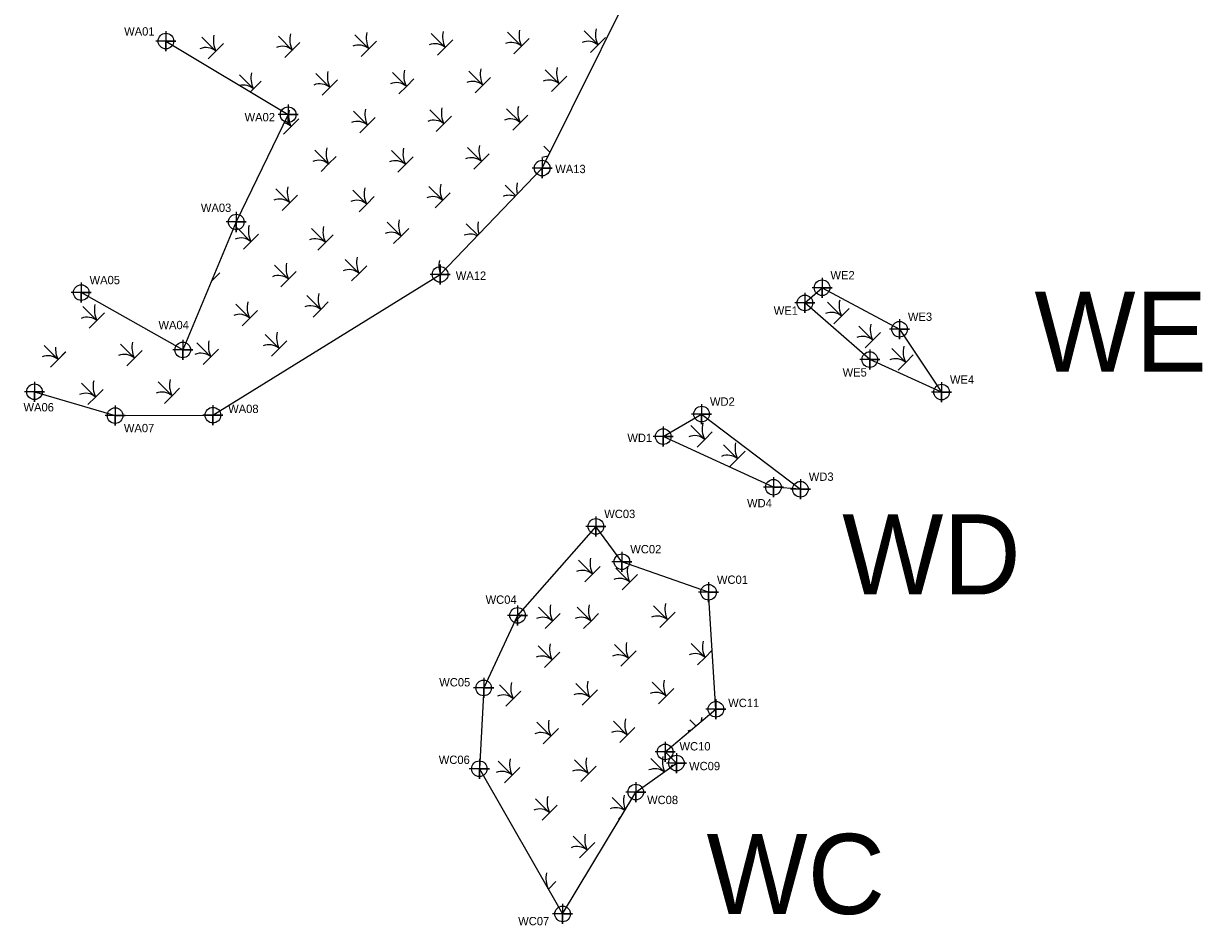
# Model space of a CAD drawing. Extents: x 2129042 to 2129395, y 148168 to 148691.
# Drawn here: x 2129042.3 to 2129395.4, y 148168.4 to 148438.5 of the extents above; entities that cross this region are included whole.
import ezdxf

# ---------------------------------------------------------------- set-up
doc = ezdxf.new("R2010")
doc.units = 0
for name, color, linetype in [('Default', 7, 'Continuous'), ('Exist Environmental Wetland Boundary', 7, 'Continuous'), ('Exist Environmental Wetland Boundary Cogo Number', 7, 'Continuous'), ('Exist Environmental Wetland Boundary Cogo Point CELL', 7, 'Continuous'), ('Exist Hydro Swamp or Marsh', 7, 'Continuous')]:
    doc.layers.add(name, color=color, linetype=linetype)

msp = doc.modelspace()

# ---------------------------------------------------------------- linework, layer by layer
at = {"layer": 'Exist Environmental Wetland Boundary'}
for points in [[(2129099.03, 148321.24), (2129167.08, 148363.39), (2129197.64, 148395.26), (2129233.05, 148466.61), (2129222.96, 148527.56), (2129235.22, 148526.74)], [(2129084.96, 148433.28), (2129121.56, 148411.25), (2129106.03, 148379.1), (2129089.99, 148340.77), (2129059.59, 148357.96)], [(2129276.33, 148354.86), (2129281.48, 148359.4), (2129304.68, 148346.97), (2129317.27, 148328.15), (2129295.76, 148337.9), (2129276.33, 148354.86)], [(2129045.59, 148328.24), (2129069.73, 148321.11), (2129099.03, 148321.24)], [(2129233.9, 148314.83), (2129245.4, 148321.55), (2129274.99, 148299.06), (2129266.91, 148299.65), (2129233.9, 148314.83)], [(2129247.48, 148268.2), (2129221.53, 148277.34), (2129213.73, 148287.91), (2129190.28, 148261.25), (2129180.12, 148239.54), (2129178.82, 148215.32), (2129203.77, 148171.84), (2129225.66, 148208.34), (2129237.86, 148217.02), (2129234.47, 148220.36), (2129249.69, 148233.15), (2129247.48, 148268.2)]]:
    msp.add_lwpolyline(points, dxfattribs=at)
at = {"layer": 'Exist Environmental Wetland Boundary Cogo Point CELL'}
for points in [[(2129084.96, 148436.28), (2129084.96, 148430.28), (2129084.96, 148433.28), (2129087.96, 148433.28), (2129081.96, 148433.28)], [(2129121.56, 148414.25), (2129121.56, 148408.25), (2129121.56, 148411.25), (2129124.56, 148411.25), (2129118.56, 148411.25)], [(2129197.64, 148398.26), (2129197.64, 148392.26), (2129197.64, 148395.26), (2129200.64, 148395.26), (2129194.64, 148395.26)], [(2129106.03, 148382.1), (2129106.03, 148376.1), (2129106.03, 148379.1), (2129109.03, 148379.1), (2129103.03, 148379.1)], [(2129167.08, 148366.39), (2129167.08, 148360.39), (2129167.08, 148363.39), (2129170.08, 148363.39), (2129164.08, 148363.39)], [(2129059.59, 148360.96), (2129059.59, 148354.96), (2129059.59, 148357.96), (2129062.59, 148357.96), (2129056.59, 148357.96)], [(2129281.48, 148362.4), (2129281.48, 148356.4), (2129281.48, 148359.4), (2129284.48, 148359.4), (2129278.48, 148359.4)], [(2129276.33, 148357.86), (2129276.33, 148351.86), (2129276.33, 148354.86), (2129279.33, 148354.86), (2129273.33, 148354.86)], [(2129304.68, 148349.97), (2129304.68, 148343.97), (2129304.68, 148346.97), (2129307.68, 148346.97), (2129301.68, 148346.97)], [(2129089.99, 148343.77), (2129089.99, 148337.77), (2129089.99, 148340.77), (2129092.99, 148340.77), (2129086.99, 148340.77)], [(2129295.76, 148340.9), (2129295.76, 148334.9), (2129295.76, 148337.9), (2129298.76, 148337.9), (2129292.76, 148337.9)], [(2129045.59, 148331.24), (2129045.59, 148325.24), (2129045.59, 148328.24), (2129048.59, 148328.24), (2129042.59, 148328.24)], [(2129317.27, 148331.15), (2129317.27, 148325.15), (2129317.27, 148328.15), (2129320.27, 148328.15), (2129314.27, 148328.15)], [(2129069.73, 148324.11), (2129069.73, 148318.11), (2129069.73, 148321.11), (2129072.73, 148321.11), (2129066.73, 148321.11)], [(2129099.03, 148324.24), (2129099.03, 148318.24), (2129099.03, 148321.24), (2129102.03, 148321.24), (2129096.03, 148321.24)], [(2129245.4, 148324.55), (2129245.4, 148318.55), (2129245.4, 148321.55), (2129248.4, 148321.55), (2129242.4, 148321.55)], [(2129233.9, 148317.83), (2129233.9, 148311.83), (2129233.9, 148314.83), (2129236.9, 148314.83), (2129230.9, 148314.83)], [(2129266.91, 148302.65), (2129266.91, 148296.65), (2129266.91, 148299.65), (2129269.91, 148299.65), (2129263.91, 148299.65)], [(2129274.99, 148302.06), (2129274.99, 148296.06), (2129274.99, 148299.06), (2129277.99, 148299.06), (2129271.99, 148299.06)], [(2129213.73, 148290.91), (2129213.73, 148284.91), (2129213.73, 148287.91), (2129216.73, 148287.91), (2129210.73, 148287.91)], [(2129221.53, 148280.34), (2129221.53, 148274.34), (2129221.53, 148277.34), (2129224.53, 148277.34), (2129218.53, 148277.34)], [(2129247.48, 148271.2), (2129247.48, 148265.2), (2129247.48, 148268.2), (2129250.48, 148268.2), (2129244.48, 148268.2)], [(2129190.28, 148264.25), (2129190.28, 148258.25), (2129190.28, 148261.25), (2129193.28, 148261.25), (2129187.28, 148261.25)], [(2129180.12, 148242.54), (2129180.12, 148236.54), (2129180.12, 148239.54), (2129183.12, 148239.54), (2129177.12, 148239.54)], [(2129249.69, 148236.15), (2129249.69, 148230.15), (2129249.69, 148233.15), (2129252.69, 148233.15), (2129246.69, 148233.15)], [(2129234.47, 148223.36), (2129234.47, 148217.36), (2129234.47, 148220.36), (2129237.47, 148220.36), (2129231.47, 148220.36)], [(2129237.86, 148220.02), (2129237.86, 148214.02), (2129237.86, 148217.02), (2129240.86, 148217.02), (2129234.86, 148217.02)], [(2129178.82, 148218.32), (2129178.82, 148212.32), (2129178.82, 148215.32), (2129181.82, 148215.32), (2129175.82, 148215.32)], [(2129225.66, 148211.34), (2129225.66, 148205.34), (2129225.66, 148208.34), (2129228.66, 148208.34), (2129222.66, 148208.34)], [(2129203.77, 148174.84), (2129203.77, 148168.84), (2129203.77, 148171.84), (2129206.77, 148171.84), (2129200.77, 148171.84)]]:
    msp.add_lwpolyline(points, dxfattribs=at)
for centre in [(2129084.96, 148433.28), (2129121.56, 148411.25), (2129197.64, 148395.26), (2129106.03, 148379.1), (2129167.08, 148363.39), (2129281.48, 148359.4), (2129059.59, 148357.96), (2129276.33, 148354.86), (2129304.68, 148346.97), (2129089.99, 148340.77), (2129295.76, 148337.9), (2129045.59, 148328.24), (2129317.27, 148328.15), (2129069.73, 148321.11), (2129099.03, 148321.24), (2129245.4, 148321.55), (2129233.9, 148314.83), (2129266.91, 148299.65), (2129274.99, 148299.06), (2129213.73, 148287.91), (2129221.53, 148277.34), (2129247.48, 148268.2), (2129190.28, 148261.25), (2129180.12, 148239.54), (2129249.69, 148233.15), (2129234.47, 148220.36), (2129237.86, 148217.02), (2129178.82, 148215.32), (2129225.66, 148208.34), (2129203.77, 148171.84)]:
    msp.add_circle(centre, 2.34, dxfattribs=at)
at = {"layer": 'Exist Hydro Swamp or Marsh'}
for p, q in [((2129179.43, 148226.74), (2129179.65, 148226.96)), ((2129235.74, 148215.52), (2129236.68, 148216.45)), ((2129220.49, 148200.26), (2129221.3, 148201.08))]:
    msp.add_line(p, q, dxfattribs=at)
for points in [[(2129120.53, 148428.33), (2129122.81, 148430.61), (2129118.63, 148434.8), (2129122.81, 148430.61), (2129125.09, 148432.89)], [(2129143.42, 148428.71), (2129145.7, 148430.99), (2129141.52, 148435.17), (2129145.7, 148430.99), (2129147.98, 148433.27)], [(2129166.31, 148429.09), (2129168.59, 148431.37), (2129164.41, 148435.55), (2129168.59, 148431.37), (2129170.87, 148433.65)], [(2129189.2, 148429.46), (2129191.48, 148431.74), (2129187.29, 148435.93), (2129191.48, 148431.74), (2129193.76, 148434.02)], [(2129212.09, 148429.84), (2129214.37, 148432.12), (2129210.18, 148436.31), (2129214.37, 148432.12), (2129216.65, 148434.4)], [(2129097.64, 148427.95), (2129099.92, 148430.23), (2129095.74, 148434.42), (2129099.92, 148430.23), (2129102.21, 148432.52)], [(2129177.56, 148417.83), (2129179.85, 148420.11), (2129175.66, 148424.3), (2129179.85, 148420.11), (2129182.13, 148422.39)], [(2129200.45, 148418.21), (2129202.73, 148420.49), (2129198.55, 148424.67), (2129202.73, 148420.49), (2129205.01, 148422.77)], [(2129110.26, 148418.05), (2129111.18, 148418.98), (2129107, 148423.16), (2129111.18, 148418.98), (2129113.46, 148421.26)], [(2129131.79, 148417.08), (2129134.07, 148419.36), (2129129.88, 148423.54), (2129134.07, 148419.36), (2129136.35, 148421.64)], [(2129154.68, 148417.45), (2129156.96, 148419.73), (2129152.77, 148423.92), (2129156.96, 148419.73), (2129159.24, 148422.01)], [(2129120.7, 148409.46), (2129122.44, 148407.72), (2129124.72, 148410)], [(2129143.04, 148405.82), (2129145.32, 148408.1), (2129141.14, 148412.29), (2129145.32, 148408.1), (2129147.6, 148410.38)], [(2129165.93, 148406.2), (2129168.21, 148408.48), (2129164.03, 148412.66), (2129168.21, 148408.48), (2129170.49, 148410.76)], [(2129188.82, 148406.57), (2129191.1, 148408.86), (2129186.92, 148413.04), (2129191.1, 148408.86), (2129193.38, 148411.14)], [(2129120.15, 148405.44), (2129122.44, 148407.72), (2129120.7, 148409.46)], [(2129131.41, 148394.19), (2129133.69, 148396.47), (2129129.51, 148400.65), (2129133.69, 148396.47), (2129135.97, 148398.75)], [(2129154.44, 148394.06), (2129156.72, 148396.34), (2129152.53, 148400.53), (2129156.72, 148396.34), (2129159, 148398.62)], [(2129177.19, 148394.94), (2129179.47, 148397.22), (2129175.28, 148401.41), (2129179.47, 148397.22), (2129181.75, 148399.5)], [(2129199.98, 148399.97), (2129198.17, 148401.78), (2129199.98, 148399.97)], [(2129119.78, 148382.55), (2129122.06, 148384.84), (2129117.87, 148389.02), (2129122.06, 148384.84), (2129124.34, 148387.12)], [(2129165.55, 148383.31), (2129167.84, 148385.59), (2129163.65, 148389.77), (2129167.84, 148385.59), (2129170.12, 148387.87)], [(2129189.71, 148386.98), (2129186.54, 148390.15), (2129189.71, 148386.98)], [(2129142.8, 148382.19), (2129145.08, 148384.47), (2129140.9, 148388.65), (2129145.08, 148384.47), (2129147.36, 148386.75)], [(2129153.1, 148372.61), (2129155.38, 148374.89), (2129151.19, 148379.07), (2129155.38, 148374.89), (2129157.66, 148377.17)], [(2129178.32, 148375.11), (2129174.91, 148378.52), (2129178.32, 148375.11)], [(2129108.14, 148370.92), (2129110.43, 148373.2), (2129106.24, 148377.39), (2129110.43, 148373.2), (2129112.71, 148375.48)], [(2129130.47, 148370.66), (2129132.75, 148372.94), (2129128.57, 148377.13), (2129132.75, 148372.94), (2129135.04, 148375.22)], [(2129140.54, 148361.43), (2129142.82, 148363.71), (2129138.64, 148367.89), (2129142.82, 148363.71), (2129145.1, 148365.99)], [(2129119.4, 148359.67), (2129121.68, 148361.95), (2129117.5, 148366.13), (2129121.68, 148361.95), (2129123.96, 148364.23)], [(2129098.62, 148361.4), (2129098.79, 148361.57), (2129098.72, 148361.64)], [(2129098.72, 148361.64), (2129098.79, 148361.57), (2129101.07, 148363.85)], [(2129129.02, 148350.59), (2129131.3, 148352.87), (2129127.11, 148357.06), (2129131.3, 148352.87), (2129133.58, 148355.15)], [(2129061.99, 148347.28), (2129064.27, 148349.56), (2129060.09, 148353.74), (2129064.27, 148349.56), (2129066.55, 148351.84)], [(2129107.77, 148348.03), (2129110.05, 148350.31), (2129105.86, 148354.5), (2129110.05, 148350.31), (2129112.33, 148352.6)], [(2129285.04, 148348.6), (2129287.32, 148350.88), (2129283.14, 148355.07), (2129287.32, 148350.88), (2129289.61, 148353.16)], [(2129294.39, 148341.42), (2129296.67, 148343.7), (2129292.49, 148347.88), (2129296.67, 148343.7), (2129298.96, 148345.98)], [(2129096.13, 148336.4), (2129098.42, 148338.68), (2129094.23, 148342.87), (2129098.42, 148338.68), (2129100.7, 148340.96)], [(2129116.57, 148338.95), (2129118.86, 148341.23), (2129114.67, 148345.41), (2129118.86, 148341.23), (2129121.14, 148343.51)], [(2129050.37, 148335.65), (2129052.65, 148337.93), (2129048.46, 148342.12), (2129052.65, 148337.93), (2129054.93, 148340.21)], [(2129050.36, 148335.65), (2129052.64, 148337.93), (2129050.95, 148339.62)], [(2129050.95, 148339.62), (2129052.64, 148337.93), (2129054.92, 148340.21)], [(2129073.25, 148336.02), (2129075.53, 148338.3), (2129071.34, 148342.49), (2129075.53, 148338.3), (2129077.81, 148340.59)], [(2129304.24, 148334.75), (2129306.52, 148337.03), (2129302.34, 148341.22), (2129306.52, 148337.03), (2129308.8, 148339.31)], [(2129061.61, 148324.39), (2129063.89, 148326.67), (2129059.71, 148330.86), (2129063.89, 148326.67), (2129066.18, 148328.95)], [(2129084.5, 148324.77), (2129086.78, 148327.05), (2129082.6, 148331.23), (2129086.78, 148327.05), (2129089.06, 148329.33)], [(2129244.03, 148311.69), (2129246.31, 148313.97), (2129242.13, 148318.16), (2129246.31, 148313.97), (2129248.59, 148316.26)], [(2129253.88, 148305.85), (2129256.16, 148308.13), (2129251.97, 148312.32), (2129256.16, 148308.13), (2129258.44, 148310.41)], [(2129210.46, 148271.32), (2129212.74, 148273.6), (2129208.56, 148277.79), (2129212.74, 148273.6), (2129215.02, 148275.88)], [(2129221.62, 148268.93), (2129223.9, 148271.21), (2129219.71, 148275.39), (2129223.9, 148271.21), (2129226.18, 148273.49)], [(2129198.49, 148257.29), (2129200.77, 148259.57), (2129196.58, 148263.75), (2129200.77, 148259.57), (2129203.05, 148261.85)], [(2129209.99, 148257.29), (2129212.27, 148259.57), (2129208.08, 148263.76), (2129212.27, 148259.57), (2129214.55, 148261.85)], [(2129232.87, 148257.67), (2129235.15, 148259.95), (2129230.97, 148264.13), (2129235.15, 148259.95), (2129237.44, 148262.23)], [(2129189.28, 148259.1), (2129189.38, 148259.2), (2129189.34, 148259.23)], [(2129189.34, 148259.23), (2129189.38, 148259.2), (2129191.66, 148261.48)], [(2129198.35, 148245.66), (2129200.63, 148247.94), (2129196.45, 148252.12), (2129200.63, 148247.94), (2129202.91, 148250.22)], [(2129221.24, 148246.04), (2129223.52, 148248.32), (2129219.34, 148252.5), (2129223.52, 148248.32), (2129225.8, 148250.6)], [(2129244.13, 148246.41), (2129246.41, 148248.69), (2129242.23, 148252.88), (2129246.41, 148248.69), (2129248.58, 148250.86)], [(2129186.72, 148234.03), (2129189, 148236.31), (2129184.82, 148240.49), (2129189, 148236.31), (2129191.28, 148238.59)], [(2129209.61, 148234.4), (2129211.89, 148236.68), (2129207.7, 148240.87), (2129211.89, 148236.68), (2129214.17, 148238.97)], [(2129232.5, 148234.78), (2129234.78, 148237.06), (2129230.59, 148241.25), (2129234.78, 148237.06), (2129237.06, 148239.34)], [(2129243.71, 148228.13), (2129241.85, 148229.99), (2129243.71, 148228.13)], [(2129197.98, 148222.77), (2129200.26, 148225.05), (2129196.07, 148229.24), (2129200.26, 148225.05), (2129202.54, 148227.33)], [(2129220.86, 148223.15), (2129223.14, 148225.43), (2129218.96, 148229.61), (2129223.14, 148225.43), (2129225.43, 148227.71)], [(2129186.34, 148211.14), (2129188.62, 148213.42), (2129184.44, 148217.6), (2129188.62, 148213.42), (2129190.9, 148215.7)], [(2129209.23, 148211.52), (2129211.51, 148213.8), (2129207.33, 148217.98), (2129211.51, 148213.8), (2129213.79, 148216.08)], [(2129234.17, 148214.4), (2129230.22, 148218.36), (2129234.17, 148214.4)], [(2129197.6, 148199.88), (2129199.88, 148202.16), (2129195.69, 148206.35), (2129199.88, 148202.16), (2129202.16, 148204.44)], [(2129222.4, 148202.91), (2129218.58, 148206.73), (2129222.4, 148202.91)], [(2129208.85, 148188.63), (2129211.13, 148190.91), (2129206.95, 148195.09), (2129211.13, 148190.91), (2129213.42, 148193.19)], [(2129199.5, 148179.28), (2129199.5, 148179.28), (2129201.78, 148181.56)], [(2129199.5, 148179.27), (2129199.5, 148179.28), (2129199.5, 148179.28)]]:
    msp.add_lwpolyline(points, dxfattribs=at)
for centre, radius, start, end in [((2129106.37, 148433.46), 7.21, 167.1274, 206.6222), ((2129129.26, 148433.84), 7.21, 167.1274, 206.6222), ((2129152.15, 148434.22), 7.21, 167.1274, 206.6222), ((2129175.03, 148434.6), 7.21, 167.1274, 206.6222), ((2129197.92, 148434.97), 7.21, 167.1274, 206.6222), ((2129220.81, 148435.35), 7.21, 167.1274, 206.6222), ((2129096.91, 148426.75), 4.61, 49.1403, 112.535), ((2129119.8, 148427.12), 4.61, 49.1403, 112.535), ((2129142.68, 148427.5), 4.61, 49.1403, 112.535), ((2129165.57, 148427.88), 4.61, 49.1403, 112.535), ((2129188.46, 148428.26), 4.61, 49.1403, 112.535), ((2129211.35, 148428.63), 4.61, 49.1403, 112.535), ((2129140.51, 148422.59), 7.21, 167.1274, 206.6222), ((2129163.4, 148422.96), 7.21, 167.1274, 206.6222), ((2129186.29, 148423.34), 7.21, 167.1274, 206.6222), ((2129209.18, 148423.72), 7.21, 167.1274, 206.6222), ((2129117.62, 148422.21), 7.21, 167.1274, 206.6222), ((2129131.05, 148415.87), 4.61, 49.1403, 112.535), ((2129153.94, 148416.25), 4.61, 49.1403, 112.535), ((2129176.83, 148416.62), 4.61, 49.1403, 112.535), ((2129199.72, 148417), 4.61, 49.1403, 112.535), ((2129108.16, 148415.49), 4.61, 49.1403, 103.7092), ((2129197.54, 148412.09), 7.21, 167.1274, 206.6222), ((2129128.88, 148410.95), 7.21, 167.1274, 206.6222), ((2129151.77, 148411.33), 7.21, 167.1274, 206.6222), ((2129174.66, 148411.71), 7.21, 167.1274, 206.6222), ((2129188.08, 148405.37), 4.61, 49.1403, 112.535), ((2129119.42, 148404.24), 4.61, 49.1403, 78.2475), ((2129142.31, 148404.61), 4.61, 49.1403, 112.535), ((2129165.2, 148404.99), 4.61, 49.1403, 112.535), ((2129140.14, 148399.7), 7.21, 167.1274, 206.6222), ((2129163.16, 148399.57), 7.21, 167.1274, 206.6222), ((2129185.91, 148400.45), 7.21, 167.1274, 206.6222), ((2129130.67, 148392.98), 4.61, 49.1403, 112.535), ((2129153.7, 148392.85), 4.61, 49.1403, 112.535), ((2129176.45, 148393.73), 4.61, 49.1403, 112.535), ((2129199.34, 148394.11), 4.61, 89.7008, 112.535), ((2129128.5, 148388.07), 7.21, 167.1274, 206.6222), ((2129151.53, 148387.7), 7.21, 167.1274, 206.6222), ((2129174.28, 148388.82), 7.21, 167.1274, 206.6222), ((2129197.17, 148389.2), 7.21, 167.1274, 193.8993), ((2129119.04, 148381.35), 4.61, 49.1403, 112.535), ((2129142.07, 148380.98), 4.61, 49.1403, 112.535), ((2129164.82, 148382.1), 4.61, 49.1403, 112.535), ((2129187.71, 148382.48), 4.61, 67.4696, 112.535), ((2129161.82, 148378.12), 7.21, 167.1274, 206.6222), ((2129185.53, 148377.56), 7.21, 167.1274, 197.0927), ((2129116.87, 148376.43), 7.21, 167.1274, 206.6222), ((2129139.2, 148376.17), 7.21, 167.1274, 206.6222), ((2129152.36, 148371.4), 4.61, 49.1403, 112.535), ((2129176.07, 148370.85), 4.61, 62.9302, 112.535), ((2129107.41, 148369.71), 4.61, 49.1403, 112.535), ((2129129.74, 148369.45), 4.61, 49.1403, 112.535), ((2129149.26, 148366.94), 7.21, 167.1274, 206.6222), ((2129173.9, 148365.93), 7.21, 167.1274, 200.1899), ((2129128.13, 148365.18), 7.21, 167.1274, 206.6222), ((2129139.8, 148360.22), 4.61, 49.1403, 112.535), ((2129095.78, 148358.08), 4.61, 49.1403, 50.3369), ((2129105.24, 148364.8), 7.21, 205.6527, 206.6222), ((2129118.66, 148358.46), 4.61, 49.1403, 112.535), ((2129137.74, 148356.1), 7.21, 167.1274, 206.6222), ((2129070.72, 148352.79), 7.21, 167.1274, 206.6222), ((2129116.49, 148353.54), 7.21, 167.1274, 206.6222), ((2129128.28, 148349.38), 4.61, 49.1403, 112.535), ((2129293.77, 148354.11), 7.21, 167.1274, 206.6222), ((2129061.37, 148345.98), 4.61, 49.1403, 112.535), ((2129107.03, 148346.83), 4.61, 49.1403, 112.535), ((2129284.31, 148347.39), 4.61, 49.1403, 112.535), ((2129303.12, 148346.93), 7.21, 167.1274, 206.6222), ((2129081.97, 148341.53), 7.21, 167.1274, 206.6222), ((2129104.86, 148341.91), 7.21, 167.1274, 206.6222), ((2129125.3, 148344.46), 7.21, 167.1274, 206.6222), ((2129293.66, 148340.21), 4.61, 49.1403, 112.535), ((2129059.08, 148341.16), 7.21, 176.3709, 206.6222), ((2129072.51, 148334.82), 4.61, 49.1403, 112.535), ((2129095.4, 148335.19), 4.61, 49.1403, 112.535), ((2129115.84, 148337.74), 4.61, 49.1403, 112.535), ((2129312.96, 148340.26), 7.21, 167.1274, 206.6222), ((2129049.62, 148334.44), 4.61, 49.1403, 112.535), ((2129049.62, 148334.44), 4.61, 49.1403, 77.3813), ((2129303.5, 148333.54), 4.61, 49.1403, 112.535), ((2129070.34, 148329.9), 7.21, 167.1274, 206.6222), ((2129093.23, 148330.28), 7.21, 167.1274, 206.6222), ((2129060.88, 148323.18), 4.61, 49.1403, 112.535), ((2129083.77, 148323.56), 4.61, 49.1403, 112.535), ((2129252.76, 148317.2), 7.21, 167.1274, 206.6222), ((2129243.29, 148310.49), 4.61, 49.1403, 112.535), ((2129262.6, 148311.36), 7.21, 167.1274, 206.6222), ((2129253.14, 148304.64), 4.61, 49.1403, 112.535), ((2129219.19, 148276.83), 7.21, 167.1274, 206.6222), ((2129230.34, 148274.44), 7.21, 167.1274, 206.6222), ((2129209.72, 148270.11), 4.61, 49.1403, 112.535), ((2129220.88, 148267.72), 4.61, 49.1403, 112.535), ((2129207.21, 148262.8), 7.21, 167.1274, 206.6222), ((2129218.71, 148262.8), 7.21, 167.1274, 206.6222), ((2129241.6, 148263.18), 7.21, 167.1274, 206.6222), ((2129186.36, 148255.71), 4.61, 49.1403, 49.7618), ((2129195.82, 148262.43), 7.21, 206.1323, 206.6222), ((2129197.75, 148256.08), 4.61, 49.1403, 112.535), ((2129209.25, 148256.09), 4.61, 49.1403, 112.535), ((2129232.14, 148256.46), 4.61, 49.1403, 112.535), ((2129207.08, 148251.17), 7.21, 167.1274, 206.6222), ((2129229.97, 148251.55), 7.21, 167.1274, 206.6222), ((2129252.85, 148251.93), 7.21, 167.1274, 206.6222), ((2129197.62, 148244.45), 4.61, 49.1403, 112.535), ((2129220.5, 148244.83), 4.61, 49.1403, 112.535), ((2129243.39, 148245.21), 4.61, 49.1403, 112.535), ((2129195.45, 148239.54), 7.21, 167.1274, 206.6222), ((2129218.33, 148239.91), 7.21, 167.1274, 206.6222), ((2129241.22, 148240.29), 7.21, 167.1274, 206.6222), ((2129185.98, 148232.82), 4.61, 49.1403, 112.535), ((2129208.87, 148233.2), 4.61, 49.1403, 112.535), ((2129231.76, 148233.57), 4.61, 49.1403, 112.535), ((2129206.7, 148228.28), 7.21, 167.1274, 206.6222), ((2129229.59, 148228.66), 7.21, 167.1274, 206.6222), ((2129252.48, 148229.04), 7.21, 167.1274, 176.7484), ((2129220.13, 148221.94), 4.61, 49.1403, 112.535), ((2129243.02, 148222.32), 4.61, 100.1791, 112.535), ((2129197.24, 148221.56), 4.61, 49.1403, 112.535), ((2129195.07, 148216.65), 7.21, 167.1274, 206.6222), ((2129217.96, 148217.03), 7.21, 167.1274, 206.6222), ((2129240.84, 148217.4), 7.21, 167.1274, 204.0757), ((2129185.61, 148209.93), 4.61, 49.1403, 112.535), ((2129208.49, 148210.31), 4.61, 49.1403, 112.535), ((2129231.38, 148210.69), 4.61, 53.2125, 112.535), ((2129206.32, 148205.39), 7.21, 167.1274, 206.6222), ((2129229.21, 148205.77), 7.21, 167.1274, 201.7523), ((2129196.86, 148198.68), 4.61, 49.1403, 112.535), ((2129219.75, 148199.05), 4.61, 55.4314, 112.535), ((2129217.58, 148194.14), 7.21, 167.1274, 206.6222), ((2129208.12, 148187.42), 4.61, 49.1403, 112.535), ((2129205.95, 148182.51), 7.21, 167.1274, 206.6222), ((2129196.48, 148175.79), 4.61, 49.1403, 49.1852)]:
    msp.add_arc(centre, radius, start, end, dxfattribs=at)

# ---------------------------------------------------------------- texts
at = {"layer": 'Default'}
for s, p in [('WE', (2129345.07, 148334.27)), ('WD', (2129287.5, 148267.52)), ('WC', (2129246.86, 148171.81))]:
    msp.add_text(s, height=24, dxfattribs=at).set_placement(p)
at = {"layer": 'Exist Environmental Wetland Boundary Cogo Number'}
for s, p in [('WA01', (2129072.44, 148434.94)), ('WA02', (2129108.51, 148409.25)), ('WA13', (2129201.56, 148393.73)), ('WA03', (2129095.42, 148382.11)), ('WA12', (2129171.77, 148361.77)), ('WE2', (2129283.98, 148361.9)), ('WA05', (2129062.09, 148360.46)), ('WE1', (2129266.99, 148351.29)), ('WE3', (2129307.18, 148349.47)), ('WA04', (2129082.72, 148346.99)), ('WE5', (2129287.62, 148332.81)), ('WE4', (2129319.77, 148330.65)), ('WD2', (2129247.9, 148324.05)), ('WA06', (2129042.3, 148322.36)), ('WA08', (2129103.59, 148321.87)), ('WA07', (2129072.36, 148316.13)), ('WD1', (2129223.16, 148313.18)), ('WD3', (2129277.49, 148301.56)), ('WD4', (2129259, 148293.63)), ('WC03', (2129216.23, 148290.41)), ('WC02', (2129224.03, 148279.84)), ('WC01', (2129249.98, 148270.7)), ('WC04', (2129180.7, 148264.72)), ('WC05', (2129166.81, 148239.98)), ('WC11', (2129253.35, 148233.79)), ('WC10', (2129238.77, 148220.8)), ('WC06', (2129166.67, 148216.76)), ('WC09', (2129241.64, 148214.88)), ('WC08', (2129229.06, 148204.73)), ('WC07', (2129190.46, 148168.43))]:
    msp.add_text(s, height=2.5, dxfattribs=at).set_placement(p)

doc.saveas('drawing.dxf')
